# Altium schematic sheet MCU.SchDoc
size A4; SheetNumber: 2; SheetTotal: 2
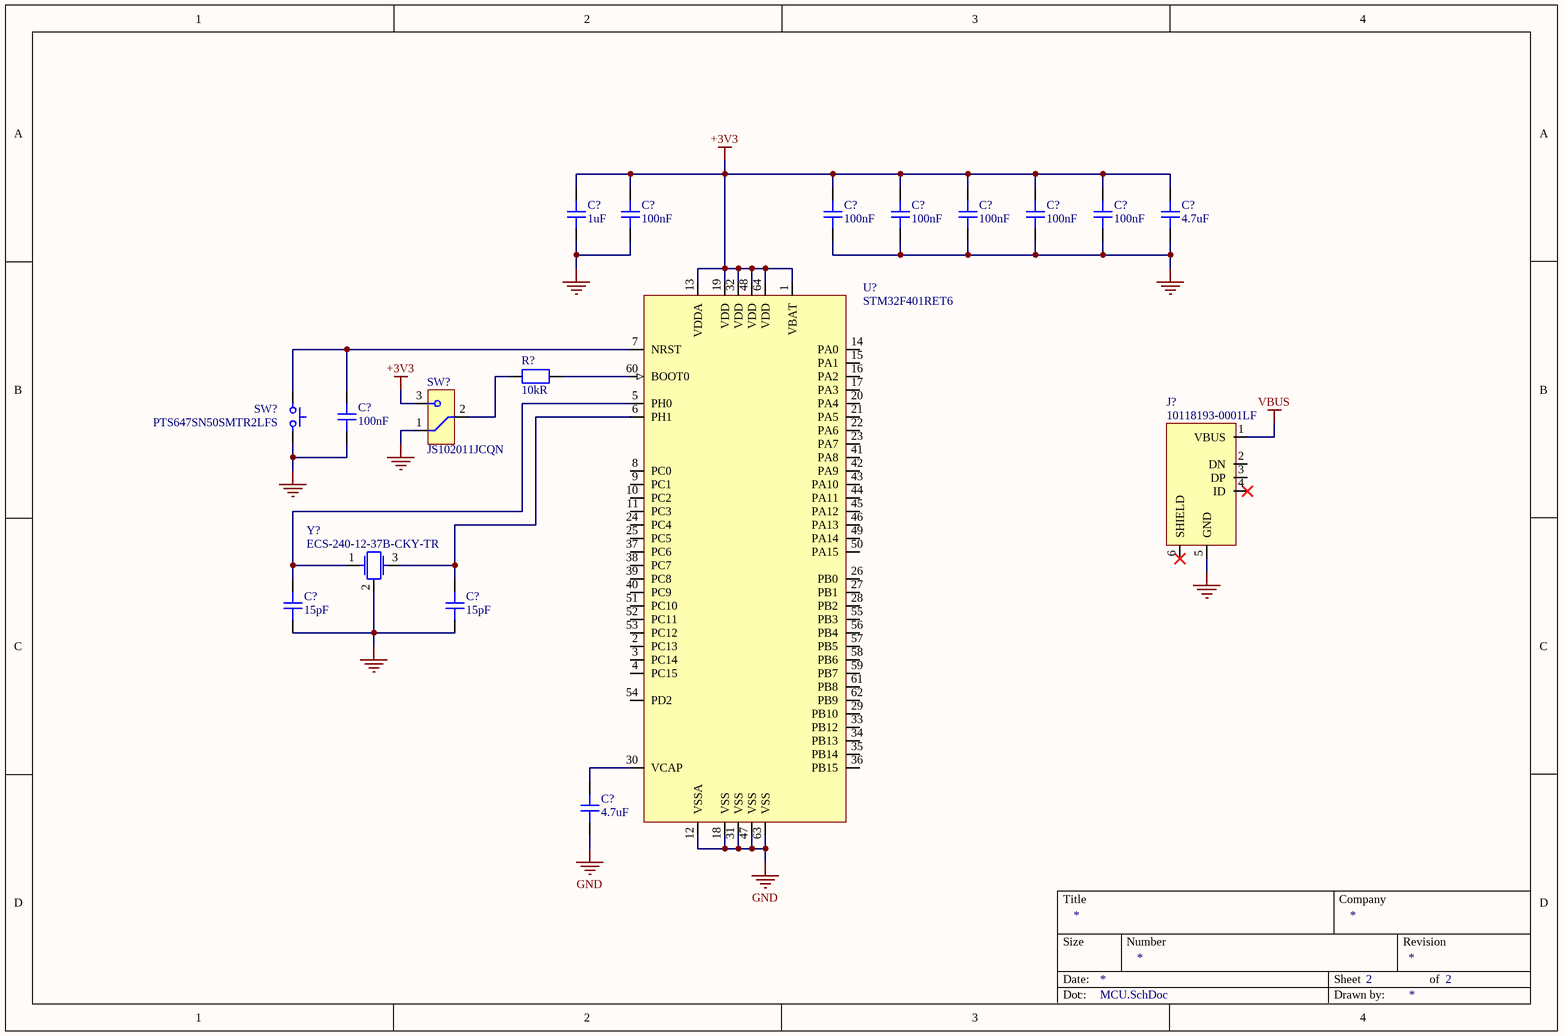
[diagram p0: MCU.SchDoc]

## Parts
(Parts that share a designator on the sheet are numbered #1, #2 ... from top to bottom, then left to right.)
C?#1  value 1uF  [CAP_0402_A]  (hidden comment: CC0402MRX5R6BB105)
C?#2  value 100nF  [CAP_0402_A]  (hidden comment: CC0402MRX5R6BB104)
C?#3  value 100nF  [CAP_0402_A]  (hidden comment: CC0402MRX5R6BB104)
C?#4  value 100nF  [CAP_0402_A]  (hidden comment: CC0402MRX5R6BB104)
C?#5  value 100nF  [CAP_0402_A]  (hidden comment: CC0402MRX5R6BB104)
C?#6  value 100nF  [CAP_0402_A]  (hidden comment: CC0402MRX5R6BB104)
C?#7  value 100nF  [CAP_0402_A]  (hidden comment: CC0402MRX5R6BB104)
C?#8  value 4.7uF  [CAP_0402_A]  (hidden comment: CC0402MRX5R6BB475)
C?#9  value 100nF  [CAP_0402_A]  (hidden comment: CC0402MRX5R6BB104)
C?#10  value 15pF  [CAP_0402_A]  (hidden comment: CC0402JRNPO9BN150)
C?#11  value 15pF  [CAP_0402_A]  (hidden comment: CC0402JRNPO9BN150)
C?#12  value 4.7uF  [CAP_0402_A]  (hidden comment: CC0402MRX5R6BB475)
J?  10118193-0001LF  [USB_MICRO-B_AMPHENOL_10118193-0001LF]
R?  value 10kR  [RES_0402_A]  (hidden comment: RC0402FR-0710KL)
SW?#1  PTS647SN50SMTR2LFS  [SW_TACTILE_SPST_NO_4.5mmX4.5mm]
SW?#2  JS102011JCQN  [JS102011JCQN]
U?  STM32F401RET6  [TSQFP50P1200X1200X160-64N]
Y?  ECS-240-12-37B-CKY-TR  [CRYSTAL_4PIN_NO_LEAD_2.0mmX1.6mm]

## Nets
+3V3: C?#1.2 C?#2.2 C?#3.2 C?#4.2 C?#5.2 C?#6.2 C?#7.2 C?#8.2 SW?#2.3 U?.1(VBAT) U?.13(VDDA) U?.19(VDD) U?.32(VDD) U?.48(VDD) U?.64(VDD)
GND: C?#1.1 C?#2.1 C?#3.1 C?#4.1 C?#5.1 C?#6.1 C?#7.1 C?#8.1 C?#9.1 C?#10.1 C?#11.1 C?#12.1 J?.5(GND) SW?#1.2 SW?#2.1 U?.12(VSSA) U?.18(VSS) U?.31(VSS) U?.47(VSS) U?.63(VSS) Y?.2
VBUS: J?.1(VBUS)
NetC?#9_2: C?#9.2 SW?#1.1 U?.7(NRST)
NetC?#10_2: C?#10.2 U?.5(PH0) Y?.1
NetC?#11_2: C?#11.2 U?.6(PH1) Y?.3
NetC?#12_2: C?#12.2 U?.30(VCAP)
NetR?_1: R?.1 SW?#2.2
NetR?_2: R?.2 U?.60(BOOT0)

Not connected (* = marked no-connect by the designer): J? 2(DN) 3(DP) 4(ID)* 6(SHIELD)*; U? 2(PC13) 3(PC14) 4(PC15) 8(PC0) 9(PC1) 10(PC2) 11(PC3) 14(PA0) 15(PA1) 16(PA2) 17(PA3) 20(PA4) 21(PA5) 22(PA6) 23(PA7) 24(PC4) 25(PC5) 26(PB0) 27(PB1) 28(PB2) 29(PB10) 33(PB12) 34(PB13) 35(PB14) 36(PB15) 37(PC6) 38(PC7) 39(PC8) 40(PC9) 41(PA8) 42(PA9) 43(PA10) 44(PA11) 45(PA12) 46(PA13) 49(PA14) 50(PA15) 51(PC10) 52(PC11) 53(PC12) 54(PD2) 55(PB3) 56(PB4) 57(PB5) 58(PB6) 59(PB7) 61(PB8) 62(PB9)

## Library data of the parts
C?#1 = CMP-001-00016-4: Multilayer Ceramic Capacitor, 1 uF, 50 V, ± 10%, X5R, 0402 [1005 Metric]; Voltage Rating (DC): 10V; Tolerance: 20%; Temperature Coefficient: 30ppm/°C
C?#2-C?#7 C?#9 = CMP-001-00009-5: Multilayer Ceramic Capacitor, 0.1 uF, 25 V, ± 20%, X7R, 0402 [1005 Metric]; Dielectric: X5R; Temperature Coefficient: 30ppm/°C; Voltage Rating: 10V
C?#8 C?#12 = CMP-001-00015-4: Multilayer Ceramic Capacitor, 4.7 uF, 50 V, ± 10%, X5R, 0402 [1005 Metric]; Tolerance: 20%; Temperature Coefficient: 30ppm/°C; Voltage Rating (DC): 10V
C?#10 C?#11 = CMP-001-00017-4: Multilayer Ceramic Capacitor, 15 pF, 10 V, ± 5%, X7R, 0402 [1005 Metric]; Insulation Resistance: 100GR; Dielectric: C0G; Voltage Rating (DC): 50V; Temperature Coefficient: 30ppm/°C
J? = CMP-002-00002-3: Usb Connector, 5 Contact(S), Female, Right Angle, Surface Mount Terminal, Locking, Receptacle; Number of Contacts: 5; Current Rating: 1.8A; Connector Type: USB,Receptacle; Pitch: 650um; Number of Ports: 1; Voltage Rating: 100V; USB Standard: USB 2.0; Insulation Resistance: 1GR
R? = CMP-009-00003-5: SMD Chip Resistor, 10 kOhm, ± 1%, 62.5 mW, 0402 [1005 Metric], Thick Film, General Purpose; Power Rating: 62.5mW; Max Power Dissipation: 63mW; Temperature Coefficient: 100ppm/°C; Voltage Rating (DC): 50V
SW?#1 = CMP-011-00000-3: Switch Tactile N.O. SPST Round Button Gull Wing 0.05A 12VDC 100000Cycles 0.98N SMD T/R; pin to pad: 1>1+2 2>3+4; Ratings: IP40; Switch Function: Off-Mom; Illumination Type: Non-Illuminated; Actuator Type: Standard; Number of Positions: 2; Operating Force: 100gf; Switch Travel: 0.25mm
SW?#2 = CMP-011-00001-1: JS Series Sub-Miniature Slide Switch SPDT On-On Top Slide 0.3A 6VDC J-Lead Surface Mount T/R; Voltage Rating (DC): 6V; Switch Travel: 2mm; Actuator Material: Nylon,Polyamide,PA46; Electrical Life: 5000Cycles; Actuator Type: Standard
U? = CMP-020-00000-3: MCU 32-bit STM32 ARM Cortex M4 RISC 512KB Flash 1.8V/2.5V/3.3V 64-Pin LQFP Tray; Operating Supply Voltage: 3.3V; Peripherals: Brown-out Detect/Reset,POR,PWM,WDT,DMA; Nominal Supply Current: 1.8uA; Number of ADC Channels: 12; Interface: I2C,SPI,USB,IrDA,SDIO,UART,USART,LIN,I2S; Clock Frequency: 84MHz; Number of USB Channels: 1; Number of Timers/Counters: 8; Number of Channels: 16; Number of PWM Channels: 23; Number of UART Channels: 3; Number of Programmable I/O: 50; Watchdog Timer: Yes; Max Power Dissipation: 313mW; Min Supply Voltage: 1.7V; Data Bus Width: 32b; RAM Size: 96KB; Max Supply Voltage: 3.6V; Oscillator Type: Internal
Y? = CMP-003-00000-1: Crystal 24MHz ±10ppm (Tol) ±10ppm (Stability) 12pF FUND 50Ohm 4-Pin Mini-CSMD T/R; pin to pad: 2>2+4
